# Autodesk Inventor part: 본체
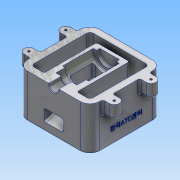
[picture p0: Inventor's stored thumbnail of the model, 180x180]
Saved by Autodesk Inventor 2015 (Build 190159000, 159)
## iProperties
Created: 2018-01
Part Number: 본체
Material: 알루미늄 6061
Document SubType Name: Modeling
Designer: SCD-A18
Density: 2.7 g/cm^3
Appearance: 알루미늄 - 평지
Mass: 995.217 g
Surface Area: 834.407 cm^2
Volume: 368.599 cm^3
Author: SCD-A18
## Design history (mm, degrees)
sketch "스케치2"
  geometry: L1 (55, -55)-(-55, -55); L2 (-55, -55)-(-55, 55); L3 (-55, 55)-(55, 55); L4 (55, 55)-(55, -55); L5 (55, -55)-(-55, 55); L6 (-55, -55)-(55, 55); 1 further point
  constraints: 12 end point, 2 midpoint, 2 parallel, 1 horizontal, 1 perpendicular
  dimensions: "d4" = 110 distance of L2.end L3.end; "d5" = 110 distance of L1.end L2.end
extrude "돌출2" new body sketch "스케치2" distance "d6" = 65; taper "d7" = 0 deg
sketch "스케치3"
  geometry: L1 (-55, 55)-(55, 55) reference; L2 (-55, -55)-(-55, 55) reference; L3 (55, -55)-(-55, -55) reference; L4 (55, 55)-(55, -55) reference; L5 (-45, 25)-(35, 25); L6 (35, 25)-(35, -25); L7 (35, -25)-(-45, -25); L8 (-45, 25)-(-45, 45); L9 (-45, 45)-(45, 45); L10 (45, 45)-(45, -45); L11 (45, -45)-(-45, -45); L12 (-45, -45)-(-45, -25); 1 further point
  constraints: 16 end point, 6 perpendicular, 1 horizontal, 1 point on line, 1 vertical
  dimensions: "d9" = 10 distance between parallel lines of L1 L9; "d10" = 10 distance between parallel lines of L2 L8; "d11" = 30 distance between parallel lines of L1 L5; "d12" = 10 distance between parallel lines of L4 L10; "d13" = 20 distance between parallel lines of L4 L6; "d14" = 10 distance between parallel lines of L3 L11; "d15" = 50 distance between parallel lines of L7 L5
extrude "돌출3" cut sketch "스케치3" stored distance "d16" = 65; taper "d17" = 0 deg
sketch "스케치4"
  geometry: L1 (35, -25)-(35, 25) reference; L2 (-55, -55)-(-55, 55) reference; L3 (-55, 0)-(35, 0); L4 (-55, 7.5)-(-36, 7.5); L5 (-36, 7.5)-(-36, 16); L6 (-36, 16)-(-22, 16); L7 (-22, 16)-(-22, 20); L8 (-22, 20)-(25, 20); L9 (25, 20)-(25, 15); L10 (25, 15)-(30, 15); L11 (30, 15)-(30, 0); L12 (-55, 7.5)-(-55, 0); 1 further point
  constraints: 20 end point, 8 perpendicular, 2 midpoint, 2 point on line, 1 collinear
  dimensions: "d18" = 15 diameter of L4 L3; "d19" = 32 diameter of L6 L3; "d20" = 40 diameter of L8 L3; "d21" = 30 diameter of L10 L3; "d22" = 19 distance from line of L5 L4.start; "d23" = 14 distance of L5.end L6.end; "d24" = 47 distance of L7.end L8.end; "d25" = 5 distance of L9.end L10.end
revolve "회전1" sketch "스케치4" stored, may be unused: angle "d26" = 180 deg
sketch "스케치5"
  geometry: L1 (17, -15)-(-20, -15); L2 (-20, -15)-(-20, 15); L3 (-20, 15)-(17, 15); L4 (17, 15)-(17, -15); L5 (17, -15)-(-20, 15); L6 (-20, -15)-(17, 15); L7 (-25, -15)-(-25, 15) reference
  constraints: 12 end point, 2 parallel, 1 horizontal, 1 perpendicular
  dimensions: "d27" = 37 distance of L2.end L3.end; "d28" = 30 distance of L1.end L2.end; "d84" = 5 distance between parallel lines of L7 L2
extrude "돌출4" cut sketch "스케치5" distance "d29" = 20; taper "d30" = 0 deg
sketch "스케치6"
  geometry: L1 (35, 0)-(35, -65) reference; L2 (35, -35)-(-45, -56.436); L3 (-45, -56.436)-(-45, -65); L4 (-45, -65)-(35, -65) reference; L5 (-55, 0)-(-55, -65) reference; L6 (-55, -35.939)-(-17, -25.757); L7 (-17, -25.757)-(-17, -20); L8 (20, -33.843)-(20, -20); L9 (20, -13.229)-(20, -20) reference; L10 (20, -33.843)-(-55, -53.939); L11 (-55, -35.939)-(-55, -53.939); L12 (-17, -20)-(20, -20); L13 (-17, -20)-(20, -20) reference; L14 (-45, -65)-(35, -65); L15 (35, -35)-(35, -65); 1 further point
  constraints: 20 end point, 4 point on line, 3 collinear, 3 vertical, 1 horizontal
  dimensions: "d31" = 30 distance of L1.end L2.start; "d32" = 105 deg angle of L3 L2; "d33" = 75 deg angle of L5 L6; "d36" = 5 distance between parallel lines of L2 L10; "d37" = 10 distance of L5.end L3.end; "d38" = 18 distance of L10.end L6.start
extrude "돌출5" cut sketch "스케치6" stored distance "d41" = 30; taper "d42" = 0 deg
extrude "돌출6" cut sketch "스케치6" stored distance "d43" = 50; taper "d44" = 0 deg
fillet "모깎기1" dims "d45" = 1
chamfer "모따기1" distance "d46" = 1; stored, may be unused: second distance "d47" = 2, angle "d48" = 45 deg
fillet "모깎기3" dims "d50" = 3
fillet "모깎기5" dims "d52" = 3
fillet "모깎기6" dims "d53" = 3
fillet "모깎기7" dims "d54" = 3
sketch "스케치7"
  geometry: L1 (-55, 55)-(55, 55) reference; L2 (-55, 8.5)-(-55, 55) reference; L3 (-55, 55)-(55, 55) reference; L4 (-35.5, 55)-(-35.5, 65); L5 (-20.5, 65)-(-20.5, 55); L6 (-35.5, 55)-(-20.5, 55); A1 r 7.5 centre (-28, 65) between (-20.5, 65) and (-35.5, 65); 1 further point
  constraints: 6 end point, 2 point on circle, 2 point on line, 2 tangent, 1 centre point, 1 collinear, 1 perpendicular, 1 vertical
  dimensions: "d55" = 10 distance from line of A1.centre L3; "d56" = 7.5 radius of A1; "d58" = 27 distance from line of A1.centre L2
extrude "돌출7" join sketch "스케치7" distance "d59" = 20; taper "d60" = 0 deg
hole "구멍1" diameter "d63" = 3.242; stored, may be unused: countersink angle "d67" = 90 deg, drill point angle "d69" = 118 deg; dims "d61" = 10, "d62" = 10, "d64" = 9, "d65" = 4, "d66" = 2, "d68" = 11
fillet "모깎기8" dims "d73" = 3
fillet "모깎기9" dims "d74" = 15
fillet "모깎기10" dims "d75" = 5
fillet "모깎기11" dims "d76" = 3
fillet "모깎기12" dims "d77" = 3
fillet "모깎기13" dims "d78" = 3
fillet "모깎기14" dims "d79" = 3
sketch "스케치9" dims "d12" = 10, "d13" = 20
  geometry: L1 (95, 0)-(80, 0) reference; L2 (-15, 65)-(-15, 0) reference; 2 further points
  constraints: 1 other
  dimensions: "d80" = 20 distance from line of L1 point (40, 20); "d81" = 55 distance from line of L2 point (40, 20)
feature "엠보싱1" sketch "스케치9" dims "d4" = 110, "d5" = 110, "d9" = 10, "d10" = 10, "d11" = 30, "d12" = 10, "d13" = 20, "d14" = 10, "d15" = 50, "d82" = 0.5, "d83" = 0
node "솔리드2"
pattern_linear "직사각형 패턴1" dims "d72" = 56
mirror "대칭1"
